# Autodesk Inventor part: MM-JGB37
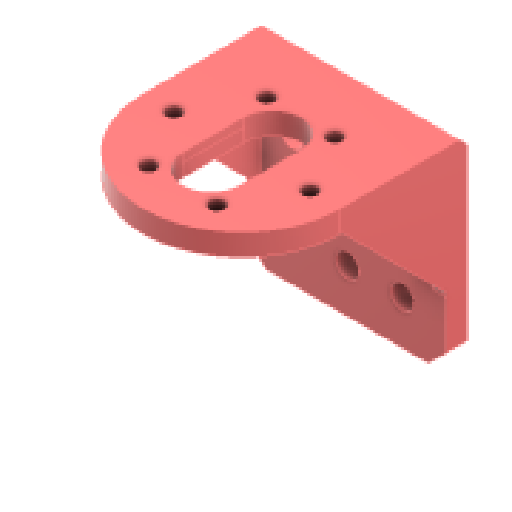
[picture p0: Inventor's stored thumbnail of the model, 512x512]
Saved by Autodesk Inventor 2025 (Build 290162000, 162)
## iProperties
Created: 2024-01
Part Number: MM-JGB37
Material: Plastica ABS
Document SubType Name: Modeling
Designer: R5800u
Density: 1.06 g/cm^3
Appearance: Liscia - Rosso
Sending System: Autodesk Translation Framework v12.14.0.127
Preprocessor: ST-DEVELOPER v20
Title: MM-JGB37 v4.step
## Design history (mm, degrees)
node "Body1"
sketch "Schizzo1"
  geometry: L1 (0, -42.5)-(0, 0) reference; L2 (40, -42.5)-(0, -42.5) reference; L3 (40, -42.5)-(40, 0) reference; L4 (0, 0)-(40, 0) reference; 1 further point
extrude "Estrusione1" join sketch "Schizzo1" distance "d0" = 2; taper "d1" = 0 deg
sketch "Schizzo3"
  geometry: L1 (20, 0)-(20, 29) reference; L2 (-20, 29)-(20, 29) reference; L3 (-20, 29)-(-20, 0) reference; L4 (-6.5, -7)-(-6.5, 7) reference; L5 (6.5, 7)-(6.5, -7) reference; C1 r 1.75 at (15.5, 0) reference; C2 r 1.75 at (-7.75, -13.423) reference; C3 r 1.75 at (7.75, -13.423) reference; C4 r 1.75 at (7.75, 13.423) reference; C5 r 1.75 at (-15.5, 0) reference; C6 r 1.75 at (-7.75, 13.423) reference; A1 r 20 centre (0, 0) between (-20, 0) and (20, 0) reference; A2 r 6.5 centre (0, 7) between (6.5, 7) and (-6.5, 7) reference; A3 r 6.5 centre (0, -7) between (-6.5, -7) and (6.5, -7) reference; 1 further point
extrude "Estrusione2" join sketch "Schizzo3" distance "d2" = 2; taper "d3" = 0 deg
sketch "Schizzo5"
  geometry: L1 (20, 0)-(20, 29) reference; L2 (20, 29)-(-20, 29) reference; L3 (-20, 29)-(-20, 0) reference; L4 (6.5, 7)-(6.5, -7) reference; L5 (-6.5, -7)-(-6.5, 7) reference; L6 (-22.5, 0)-(-22.5, 31.5); L7 (-22.5, 31.5)-(22.5, 31.5); L8 (22.5, 31.5)-(22.5, 0); L9 (22.5, 29)-(20, 29); L10 (-22.5, 29)-(-20, 29); C1 r 1.75 at (-7.75, 13.423) reference; C2 r 1.75 at (-15.5, 0) reference; C3 r 1.75 at (7.75, 13.423) reference; C4 r 1.75 at (7.75, -13.423) reference; C5 r 1.75 at (-7.75, -13.423) reference; C6 r 1.75 at (15.5, 0) reference; A1 r 20 centre (0, 0) between (-20, 0) and (20, 0) reference; A2 r 6.5 centre (0, -7) between (-6.5, -7) and (6.5, -7) reference; A3 r 6.5 centre (0, 7) between (6.5, 7) and (-6.5, 7) reference; A4 r 22.5 centre (0, 0) between (-22.5, 0) and (22.5, 0); 1 further point
  constraints: 10 end point, 3 point on line, 2 perpendicular, 2 point on circle, 1 centre point, 3 other
  dimensions: "d5" = 2.5 radial gap between concentric circles of A1 A4
extrude "Estrusione3" join sketch "Schizzo5" stored distance "d6" = 2; taper "d7" = 0 deg
sketch "Schizzo6"
  geometry: L1 (-2.5, -5)-(-2.5, 24) reference; L2 (42.5, 24)-(42.5, -5) reference; L3 (-2.5, -5)-(42.5, -5); L4 (42.5, -5)-(42.5, 0); L5 (42.5, 0)-(-2.5, 0); L6 (-2.5, 0)-(-2.5, -5); L7 (0, 0)-(40, 0) reference; L8 (0, -5)-(0, 0) reference; L9 (40, -5)-(0, -5) reference; L10 (40, -5)-(40, 0) reference; 3 further points
  constraints: 8 end point, 2 parallel, 2 point on line, 1 horizontal, 1 perpendicular
extrude "Estrusione4" join sketch "Schizzo6" stored distance "d8" = 10; taper "d9" = 0 deg
sketch "Schizzo7"
  geometry: L1 (5, -5)-(29, -5) reference; L2 (29, 0)-(29, -5) reference; L3 (0, 0)-(29, 0) reference; L4 (0, 0)-(0, -44.5) reference; L5 (5, -44.5)-(0, -44.5) reference; L6 (5, -44.5)-(5, -5) reference; L7 (27.973, -5.631)-(5, -28.604); A1 r 1.151 centre (29, -6.151) between (29, -5) and (27.973, -5.631); 1 further point
  constraints: 2 end point, 2 point on circle, 1 centre point, 1 point on line, 1 tangent
  dimensions: "d10" = 45 deg angle of L6 L7
extrude "Estrusione5" join sketch "Schizzo7" distance "d11" = 3; taper "d12" = 0 deg
node "Piano di lavoro1"
mirror "Speculare1"
fillet "Raccordo1" dims "d13" = 2
sketch "Schizzo8"
  geometry: L1 (10, -180.5)-(10, 19.5) reference; L2 (0, 29.5)-(300, 29.5) reference; L3 (45, 0)-(0, 0) reference; L4 (45, 0)-(45, 15.067) reference; L5 (0, 16.481)-(0, 38.869) reference; L6 (0, 0)-(0, 15.067) reference; 8 further points
  constraints: 4 point on line, 1 midpoint
  dimensions: "d16" = 10 distance from line of L3 point (10, 10); "d17" = 10 distance from line of L4 point (35, 29.5); "d18" = 12.5 distance of point (35, 29.5) point (22.5, 29.5); "d29" = 10.00001 distance from line of L5 point (10, 29.5); "d30" = 45 distance from line of point (0, 7.534) L4 (derived)
  node "Riferimento1"
  node "Riferimento2"
hole "Foro1" sketch "Schizzo8" diameter "d19" = 5.3; stored, may be unused: countersink angle "d23" = 89.9544 deg, drill point angle "d25" = 118 deg; dims "d20" = 6, "d21" = 9.4, "d22" = 2, "d24" = 8
chamfer "Smusso1" distance "d26" = 4; stored, may be unused: second distance "d27" = 2, angle "d28" = 45 deg
chamfer "Smusso2" distance "d31" = 2; stored, may be unused: second distance "d32" = 2, angle "d33" = 45 deg
node "Solido1"
node "Linea chiusa proiettata1"
node "Linea chiusa proiettata2"
node "Linea chiusa proiettata3"
node "Linea chiusa proiettata4"
node "Linea chiusa proiettata5"
